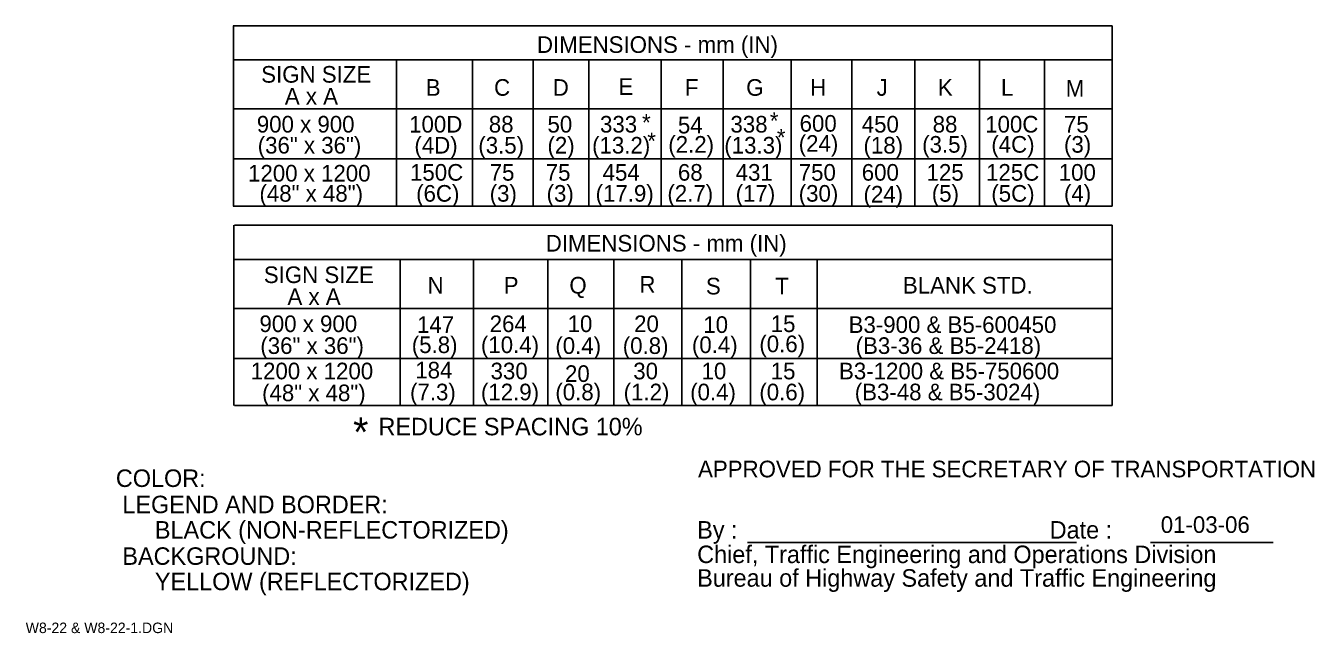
# Model space of a CAD drawing. Extents: x 0.012 to 0.196, y 0.004 to 0.259.
# Drawn here: x 0.0124 to 0.1964, y 0.004 to 0.0908 of the extents above; entities that cross this region are included whole.
import ezdxf

# ---------------------------------------------------------------- set-up
doc = ezdxf.new("R2010")
doc.units = 0
for name, color, linetype in [('1', 7, 'Continuous'), ('3', 7, 'Continuous'), ('4', 7, 'Continuous')]:
    doc.layers.add(name, color=color, linetype=linetype)

msp = doc.modelspace()

# ---------------------------------------------------------------- linework, layer by layer
at = {"layer": '1'}
for p, q in [((0.11543984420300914, 0.01694517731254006), (0.1624214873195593, 0.01694517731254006)), ((0.17295324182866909, 0.01694517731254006), (0.1905000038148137, 0.01694517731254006))]:
    msp.add_line(p, q, dxfattribs=at)
at = {"layer": '3'}
for p, q in [((0.1675, 0.09075), (0.042, 0.09075)), ((0.0420538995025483, 0.09075340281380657), (0.0420538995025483, 0.06500340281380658)), ((0.16750747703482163, 0.09075340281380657), (0.16750747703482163, 0.06499713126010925)), ((0.16750747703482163, 0.08587840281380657), (0.0420538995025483, 0.08587840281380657)), ((0.0653038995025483, 0.08587840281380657), (0.0653038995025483, 0.06500340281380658)), ((0.0761597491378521, 0.08587840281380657), (0.0761597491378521, 0.06500340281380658)), ((0.08485048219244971, 0.08587840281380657), (0.08485048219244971, 0.06500340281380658)), ((0.09279507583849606, 0.08587840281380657), (0.09279507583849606, 0.06500340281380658)), ((0.10312377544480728, 0.08587840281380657), (0.10312377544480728, 0.06500340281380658)), ((0.11197470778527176, 0.08587840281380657), (0.11197470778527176, 0.06500340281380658)), ((0.12167861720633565, 0.08587840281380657), (0.12167861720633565, 0.06500340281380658)), ((0.13035576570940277, 0.08587840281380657), (0.13035576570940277, 0.06500340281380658)), ((0.13934176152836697, 0.08587840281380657), (0.13934176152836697, 0.06499713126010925)), ((0.14857814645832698, 0.08587840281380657), (0.14857814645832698, 0.06499713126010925)), ((0.15786147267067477, 0.08587840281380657), (0.15786147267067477, 0.06499713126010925)), ((0.16750747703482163, 0.07887840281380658), (0.0420538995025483, 0.07887840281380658)), ((0.16750747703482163, 0.07175340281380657), (0.0420538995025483, 0.07175340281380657)), ((0.1675, 0.065), (0.042, 0.065)), ((0.04210524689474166, 0.06227871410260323), (0.04210524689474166, 0.036497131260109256)), ((0.16750747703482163, 0.06224713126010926), (0.042166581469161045, 0.06224713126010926)), ((0.16750747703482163, 0.06227871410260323), (0.16750747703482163, 0.036497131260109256)), ((0.16750747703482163, 0.05736272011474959), (0.04210524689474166, 0.05736272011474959)), ((0.06582451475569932, 0.05740371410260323), (0.06582451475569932, 0.036528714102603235)), ((0.07630761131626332, 0.05740371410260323), (0.07630761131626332, 0.036528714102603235)), ((0.08692630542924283, 0.05740371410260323), (0.08692630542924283, 0.036528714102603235)), ((0.096366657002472, 0.05740371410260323), (0.096366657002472, 0.036528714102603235)), ((0.10604923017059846, 0.05740371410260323), (0.10604923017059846, 0.036528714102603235)), ((0.11586017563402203, 0.05740371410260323), (0.11586017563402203, 0.036528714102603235)), ((0.12539155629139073, 0.05736272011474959), (0.12539155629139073, 0.036528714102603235)), ((0.16750747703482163, 0.05036272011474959), (0.04210524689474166, 0.05036272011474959)), ((0.16750747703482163, 0.04323772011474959), (0.04210524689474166, 0.04323772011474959)), ((0.16750747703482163, 0.036497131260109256), (0.042166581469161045, 0.036497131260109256))]:
    msp.add_line(p, q, dxfattribs=at)

# ---------------------------------------------------------------- texts
at = {"layer": '1'}
for s, height, p in [('APPROVED FOR THE SECRETARY OF TRANSPORTATION', 0.0023752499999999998, (0.108375, 0.02625)), ('COLOR:', 0.0024997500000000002, (0.02525, 0.024875)), (' LEGEND AND BORDER:', 0.0024997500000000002, (0.02525, 0.021125)), ('      BLACK (NON-REFLECTORIZED)', 0.0024997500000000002, (0.02525, 0.0175)), ('By :                                                Date :', 0.0024997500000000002, (0.10825, 0.0175)), ('Chief, Traffic Engineering and Operations Division', 0.0024997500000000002, (0.10825, 0.014)), (' BACKGROUND:', 0.0024997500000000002, (0.02525, 0.01375)), ('Bureau of Highway Safety and Traffic Engineering', 0.0024997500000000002, (0.10825, 0.010625)), ('      YELLOW (REFLECTORIZED)', 0.0024997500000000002, (0.02525, 0.010125)), ('W8-22 & W8-22-1.DGN', 0.0015, (0.012375, 0.004))]:
    msp.add_text(s, height=height, dxfattribs=at).set_placement(p)
at = {"layer": '3'}
for s, height, p in [('DIMENSIONS - mm (IN)', 0.0023752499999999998, (0.085375, 0.08687500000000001)), ('SIGN SIZE', 0.0023752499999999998, (0.046, 0.082625)), ('B', 0.0023752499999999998, (0.0695, 0.08075)), ('C', 0.0023752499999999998, (0.07925, 0.08075)), ('D', 0.0023752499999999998, (0.08762500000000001, 0.08075)), ('E', 0.0023752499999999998, (0.097, 0.080875)), ('F', 0.0023752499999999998, (0.1065, 0.08075)), ('G', 0.0023752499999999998, (0.11525, 0.08075)), ('H', 0.0023752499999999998, (0.124375, 0.08075)), ('J', 0.0023752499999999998, (0.133875, 0.08075)), ('K', 0.0023752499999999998, (0.142625, 0.08075)), ('L', 0.0023752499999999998, (0.151625, 0.08075)), ('M', 0.0023752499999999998, (0.160875, 0.080625)), ('A x A', 0.0023752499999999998, (0.049375, 0.0795)), ('900 x 900', 0.0023752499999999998, (0.045375, 0.0755)), ('100D', 0.0023752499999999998, (0.067125, 0.0755)), ('88', 0.0023752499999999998, (0.0785, 0.0755)), ('50', 0.0023752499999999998, (0.08687500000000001, 0.0755)), ('333', 0.0023752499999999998, (0.094375, 0.0755)), ('*', 0.0023752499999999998, (0.100375, 0.07575)), ('54', 0.0023752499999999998, (0.1055, 0.075375)), ('338', 0.0023752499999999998, (0.113, 0.0755)), ('*', 0.0023752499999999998, (0.11862500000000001, 0.076)), ('600', 0.0023752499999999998, (0.122875, 0.075625)), ('450', 0.0023752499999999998, (0.13175, 0.0755)), ('88', 0.0023752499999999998, (0.141875, 0.0755)), ('100C', 0.0023752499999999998, (0.149375, 0.0755)), ('75', 0.0023752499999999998, (0.160625, 0.0755)), ('*', 0.0023752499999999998, (0.101125, 0.073125)), ('*', 0.0023752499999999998, (0.11962500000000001, 0.073625)), ('(36" x 36")', 0.0023752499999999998, (0.0455, 0.0725)), ('(4D)', 0.0023752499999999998, (0.067875, 0.0725)), ('(3.5)', 0.0023752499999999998, (0.077, 0.0725)), ('(2)', 0.0023752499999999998, (0.08687500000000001, 0.0725)), ('(13.2)', 0.0023752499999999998, (0.09325, 0.0725)), ('(2.2)', 0.0023752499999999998, (0.104125, 0.072625)), ('(13.3)', 0.0023752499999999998, (0.112125, 0.0725)), ('(24)', 0.0023752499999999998, (0.12275, 0.07275)), ('(18)', 0.0023752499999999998, (0.132, 0.0725)), ('(3.5)', 0.0023752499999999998, (0.140375, 0.072625)), ('(4C)', 0.0023752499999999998, (0.15025, 0.072625)), ('(3)', 0.0023752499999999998, (0.160625, 0.072625)), ('1200 x 1200', 0.0023752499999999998, (0.044125, 0.0685)), ('150C', 0.0023752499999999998, (0.06725, 0.068625)), ('75', 0.0023752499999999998, (0.078625, 0.068625)), ('75', 0.0023752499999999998, (0.08662500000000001, 0.068625)), ('454', 0.0023752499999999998, (0.09475, 0.068625)), ('68', 0.0023752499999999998, (0.1055, 0.068625)), ('431', 0.0023752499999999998, (0.11375, 0.068625)), ('750', 0.0023752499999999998, (0.12275, 0.068625)), ('600', 0.0023752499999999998, (0.13175, 0.068625)), ('125', 0.0023752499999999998, (0.14100000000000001, 0.068625)), ('125C', 0.0023752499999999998, (0.1495, 0.068625)), ('100', 0.0023752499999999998, (0.15987500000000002, 0.068625)), ('(48" x 48")', 0.0023752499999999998, (0.04575, 0.065625)), ('(6C)', 0.0023752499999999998, (0.068125, 0.065625)), ('(3)', 0.0023752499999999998, (0.078625, 0.065625)), ('(3)', 0.0023752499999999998, (0.08675000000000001, 0.065625)), ('(17.9)', 0.0023752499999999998, (0.09375, 0.065625)), ('(2.7)', 0.0023752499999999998, (0.10400000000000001, 0.065625)), ('(17)', 0.0023752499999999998, (0.11375, 0.065625)), ('(30)', 0.0023752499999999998, (0.12275, 0.065625)), ('(5)', 0.0023752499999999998, (0.14175000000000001, 0.065625)), ('(5C)', 0.0023752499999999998, (0.15025, 0.065625)), ('(4)', 0.0023752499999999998, (0.160625, 0.065625)), ('(24)', 0.0023752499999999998, (0.132, 0.0655)), ('DIMENSIONS - mm (IN)', 0.0023752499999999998, (0.08662500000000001, 0.0585)), ('SIGN SIZE', 0.0023752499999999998, (0.046375, 0.054)), ('N', 0.0023752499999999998, (0.06975, 0.0525)), ('P', 0.0023752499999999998, (0.080625, 0.0525)), ('Q', 0.0023752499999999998, (0.09, 0.0525)), ('R', 0.0023752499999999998, (0.1, 0.052625)), ('S', 0.0023752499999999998, (0.1095, 0.052375)), ('T', 0.0023752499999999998, (0.11937500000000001, 0.052375)), ('BLANK STD.', 0.0023752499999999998, (0.137625, 0.0525)), ('A x A', 0.0023752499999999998, (0.04975, 0.050875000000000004)), ('900 x 900', 0.0023752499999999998, (0.04575, 0.047)), ('147', 0.0023752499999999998, (0.06825, 0.046875)), ('264', 0.0023752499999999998, (0.078625, 0.047)), ('10', 0.0023752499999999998, (0.08975, 0.047)), ('20', 0.0023752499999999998, (0.09925, 0.047)), ('10', 0.0023752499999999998, (0.109125, 0.046875)), ('15', 0.0023752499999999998, (0.11875000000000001, 0.047)), ('B3-900 & B5-600450', 0.0023752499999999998, (0.129875, 0.046875)), ('(36" x 36")', 0.0023752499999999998, (0.045875, 0.043875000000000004)), ('(5.8)', 0.0023752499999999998, (0.0675, 0.044)), ('(10.4)', 0.0023752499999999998, (0.077375, 0.044)), ('(0.4)', 0.0023752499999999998, (0.088, 0.043875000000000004)), ('(0.8)', 0.0023752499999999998, (0.097625, 0.043875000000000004)), ('(0.4)', 0.0023752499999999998, (0.1075, 0.044)), ('(0.6)', 0.0023752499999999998, (0.117125, 0.044125)), ('(B3-36 & B5-2418)', 0.0023752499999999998, (0.130875, 0.043875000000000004)), ('1200 x 1200', 0.0023752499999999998, (0.0445, 0.04025)), ('184', 0.0023752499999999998, (0.068, 0.040375)), ('330', 0.0023752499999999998, (0.07875, 0.04025)), ('30', 0.0023752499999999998, (0.099125, 0.04025)), ('10', 0.0023752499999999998, (0.108875, 0.04025)), ('15', 0.0023752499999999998, (0.11875000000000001, 0.04025)), ('B3-1200 & B5-750600', 0.0023752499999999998, (0.1285, 0.04025)), ('20', 0.0023752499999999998, (0.089375, 0.039875)), ('(48" x 48")', 0.0023752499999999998, (0.046125, 0.037125)), ('(7.3)', 0.0023752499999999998, (0.06725, 0.03725)), ('(12.9)', 0.0023752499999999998, (0.077375, 0.03725)), ('(0.8)', 0.0023752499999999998, (0.088, 0.03725)), ('(1.2)', 0.0023752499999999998, (0.09775, 0.03725)), ('(0.4)', 0.0023752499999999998, (0.10725, 0.03725)), ('(0.6)', 0.0023752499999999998, (0.117125, 0.03725)), ('(B3-48 & B5-3024)', 0.0023752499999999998, (0.13075, 0.03725)), ('*', 0.004205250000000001, (0.059125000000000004, 0.030625)), ('REDUCE SPACING 10%', 0.0024997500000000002, (0.06275, 0.03225))]:
    msp.add_text(s, height=height, dxfattribs=at).set_placement(p)
at = {"layer": '4'}
msp.add_text('01-03-06', height=0.0023752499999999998, dxfattribs=at).set_placement((0.17444176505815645, 0.01830713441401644))

doc.saveas('drawing.dxf')
